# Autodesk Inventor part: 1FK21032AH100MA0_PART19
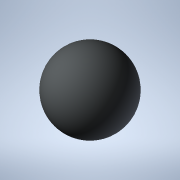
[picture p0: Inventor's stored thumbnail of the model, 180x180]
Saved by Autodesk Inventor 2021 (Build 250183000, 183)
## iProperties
Created: 2025-04
Part Number: 1FK21032AH100MA0_PART19
Material: Generic
Catalog Web Link: www.3dfindit.com
Description: -Servo synchronous motor
Document SubType Name: Modeling
Designer: psAdmin
Mass: 0.113097 g
Surface Area: 1.13097 cm^2
Volume: 0.113097 cm^3
Density: 1 g/cm^3
Appearance: PSOLRGB-212-217-219
Category: PARTsolutions
Title: 1FK21032AH100MA0_PART19
Author: Cadenas PARTsolutions
Comments: Servo synchronous motor
Sending System: PARTsolutions
Preprocessor: ST-DEVELOPER v19.3
PSOL_IDENT_0: {$CADENAS_DATA/23d-libs/siemens_ag/_cat_/12/33/1fk21032ah100ma0.prj},216 {VTYP=3D},{NB=1FK21032AH100
PSOL_IDENT_1: MA0_PART19},{LINA=1FK21032AH100MA0_PART19},{NN=1FK21032AH100MA0_PART19},{NOPRJ=TRUE},{DATE=19.08.202
PSOL_IDENT_2: 5 14:00:27},{GEOMDATE=30.07.2025 02:02:58},{VERSION=},{LINEID=10},{WBVAR=},{WBNUMERIC=}  {NB=1FK2103
PSOL_IDENT_3: 2AH100MA0_PART19},{LINA=1FK21032AH100MA0_PART19},{KT=DUMMY},{PREVIEW=../../../_pool_/d3/78/p_d211_xx
PSOL_IDENT_4: _00934j.png},{DESCSHORT=SIMOTICS S-1FK2 HD, SINAMICS S210 3AC 400V-480V, 0.59 Nm, 4500 rpm},{DESCLON
PSOL_IDENT_5: G=SIMOTICS S-1FK2 HD servo motor M0=0.64 Nm; PN = 0.28 kW at nN=4500 rpm (380-480 V); PN = 0.167 kW
PSOL_IDENT_6: at nN=2500 rpm (200-240 V); with holding brake; degree of protection IP64; cylindrical shaft D14 x 3
PSOL_IDENT_7: 0 mm; absolute encoder 22-bit + 12-bit multiturn (encoder AM22DQC); with OCC interface; plug size M1
PSOL_IDENT_8: 7, rotatable; SIMOTICS S-1FK2 servomotorfor a wide range of uses in industrial environments. SIMOTIC
PSOL_IDENT_9: S S‑1FK2 servomotors are compact synchronous motors with a high dynamic performance that set themsel
PSOL_IDENT_10: ves apart as a result of their high power density, degree of protection and overload capability. The
PSOL_IDENT_11: motors are available in two variants: as High Dynamic variant (highest dynamic performance as a res
PSOL_IDENT_12: ult of the low intrinsic moment of inertia for applications demanding a high dynamic performance wit
PSOL_IDENT_13: h low moved masses) - and as Compact variant (precise and stable closed-loop control for medium up t
PSOL_IDENT_14: o large moved masses as a result of a medium intrinsic moment of inertia). SIMOTICSS‑1FK2 servomotor
PSOL_IDENT_15: s fully exploit their strengths in a system with the SINAMICSS210 frequency converter and simple con
PSOL_IDENT_16: nection using the one cable connection (OCC). Advantages include the short control and positioning t
PSOL_IDENT_17: imes, fast and precise correction of disturbing quantities as well as stable control with a high dyn
PSOL_IDENT_18: amic performance. The servo motors can be configured to address a wide range of requirements. For ex
PSOL_IDENT_19: ample with and without holding brake, IP64 or IP65 degree of protection, singleturn or multiturn abs
PSOL_IDENT_20: olute encoders - to name just a few. Further, the servomotors are available in different shaft heigh
PSOL_IDENT_21: ts extending from 20 to 100. A shaft sealing ring is available to achieve an IP65 degree of protecti
PSOL_IDENT_22: on and for subsequent mounting at the motor or as spare part. SIMOTICS - the optimum motor for each
PSOL_IDENT_23: and every motion control application.},{INTNO=195125315563},{SUPPLIERALTNO=1FK2103-2AH10-0MA0},{MANU
PSOL_IDENT_24: ID=1FK21032AH100MA0},{MANUNAME=Siemens},{MANUTYPEDESC=SYNCHRONOUS MOTOR 1FK2 HD 0,64 NM},{AAU732=SIM
PSOL_IDENT_25: OTICS},{AAO057=S-1FK2},{AAU734=SIMOTICS S-1FK2 HD servo motor M0=0.64 Nm; PN = 0.28 kW at nN=4500 rp
PSOL_IDENT_26: m (380-480 V); PN = 0.167 kW at nN=2500 rpm (200-240 V); with holding brake; degree of protection IP
PSOL_IDENT_27: 64; cylindrical shaft D14 x 30 mm; absolute encoder 22-bit + 12-bit multiturn (encoder AM22DQC); wit
PSOL_IDENT_28: h OCC interface; plug size M17, rotatable;},{AAW338=SYNCHRONOUS MOTOR 1FK2 HD 0,64 NM},{AAO742=SIMOT
PSOL_IDENT_29: ICS},{AAO663=4034106444723},{NOCUPEROU=1},{PRICEQUANTITY=1},{QUANTITYMIN=1},{QUANTITYINT=1},{CTN=850
PSOL_IDENT_30: 15100},{COO=RO},{AAO676=1FK2103-2AH10-0MA0},{AAO677=Siemens AG},{ORDERUNIT=C62},{CONTENTUNIT=C62}
NB: 1FK21032AH100MA0_PART19
NT: Servo synchronous motor
NBSYN: $MANUID._PART19
LINA: 1FK21032AH100MA0_PART19
CATALOG: SIEMENS
PREVIEW: ../../../_pool_/d3/78/p_d211_xx_00934j.png
DESCSHORT: SIMOTICS S-1FK2 HD, SINAMICS S210 3AC 400V-480V, 0.59 Nm, 4500 rpm
DESCLONG: SIMOTICS S-1FK2 HD servo motor M0=0.64 Nm; PN = 0.28 kW at nN=4500 rpm (380-480 V); PN = 0.167 kW at nN=2500 rpm (200-240 V); with holding brake; degree of prot
INTNO: 195125315563
SUPPLIERALTNO: 1FK2103-2AH10-0MA0
MANUID: 1FK21032AH100MA0
MANUNAME: Siemens
MANUTYPEDESC: SYNCHRONOUS MOTOR 1FK2 HD 0,64 NM
AAU732: SIMOTICS
AAO057: S-1FK2
AAU734: SIMOTICS S-1FK2 HD servo motor M0=0.64 Nm; PN = 0.28 kW at nN=4500 rpm (380-480 V); PN = 0.167 kW at nN=2500 rpm (200-240 V); with holding brake; degree of prot
AAW338: SYNCHRONOUS MOTOR 1FK2 HD 0,64 NM
AAO742: SIMOTICS
AAO663: 4034106444723.0
NOCUPEROU: 1
PRICEQUANTITY: 1
QUANTITYMIN: 1
QUANTITYINT: 1
CTN: 85015100
COO: RO
ARTICLENO: 1FK21032AH100MA0_PART19
BOMINFO: 1FK21032AH100MA0_PART19
CREATOR: CADENAS GmbH
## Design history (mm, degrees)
feature "2025_04_17_15_06_16_0705"
body "Solid1"
